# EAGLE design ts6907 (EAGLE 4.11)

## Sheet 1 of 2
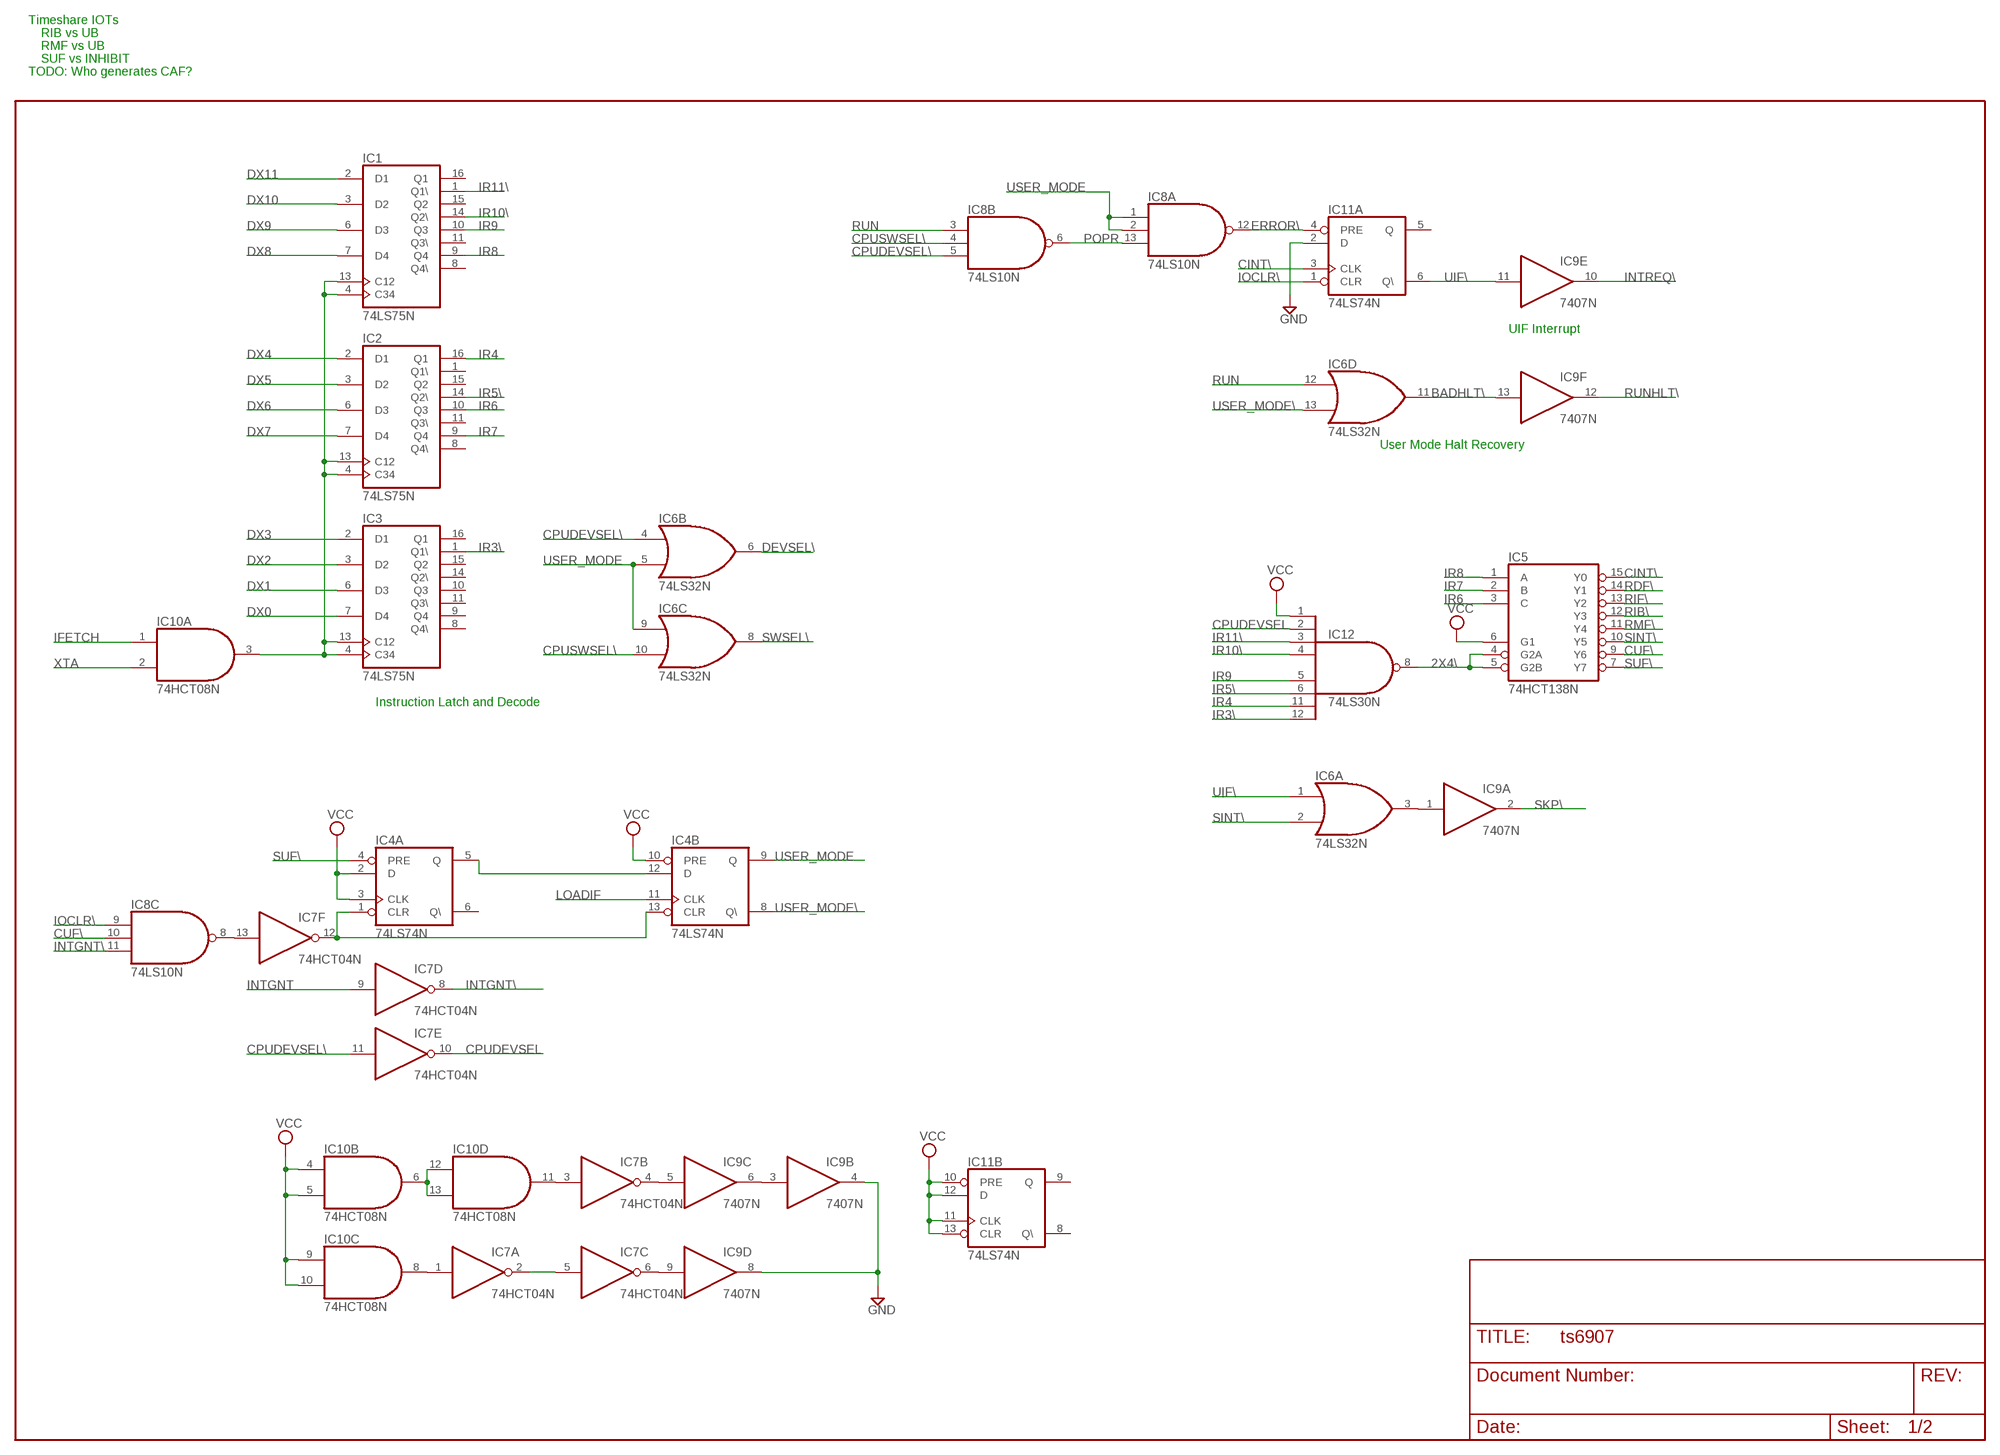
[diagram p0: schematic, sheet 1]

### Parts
IC1  74LS75N  [DIL16]
IC2  74LS75N  [DIL16]
IC3  74LS75N  [DIL16]
IC4  74LS74N  [DIL14]
IC5  74HCT138N  [DIL16]
IC6  74LS32N  [DIL14]
IC7  74HCT04N  [DIL14]
IC8  74LS10N  [DIL14]
IC9  7407N  [DIL14]
IC10  74HCT08N  [DIL14]
IC11  74LS74N  [DIL14]
IC12  74LS30N  [DIL14]

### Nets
2X4\: IC5.4(G2A) IC5.5(G2B) IC12.8(O)
BADHLT\: IC6.11(D:O) IC9.13(F:I)
CINT\: IC5.15(Y0) IC11.3(A:CLK)
CPUDEVSEL: IC7.10(E:O) IC12.2(I1)
CPUDEVSEL\: IC6.4(B:I0) IC7.11(E:I) IC8.5(B:I2) ; also sheet 2
CPUSWSEL\: IC6.10(C:I1) IC8.4(B:I1) ; also sheet 2
CUF\: IC5.9(Y6) IC8.10(C:I1)
DEVSEL\: IC6.6(B:O) ; also sheet 2
DX0: IC3.7(D4) ; also sheet 2
DX1: IC3.6(D3) ; also sheet 2
DX2: IC3.3(D2) ; also sheet 2
DX3: IC3.2(D1) ; also sheet 2
DX4: IC2.2(D1) ; also sheet 2
DX5: IC2.3(D2) ; also sheet 2
DX6: IC2.6(D3) ; also sheet 2
DX7: IC2.7(D4) ; also sheet 2
DX8: IC1.7(D4) ; also sheet 2
DX9: IC1.6(D3) ; also sheet 2
DX10: IC1.3(D2) ; also sheet 2
DX11: IC1.2(D1) ; also sheet 2
ERROR\: IC8.12(A:O) IC11.4(A:PRE)
GND: IC9.4(B:O) IC9.8(D:O) IC11.2(A:D) ; also sheet 2
IFETCH: IC10.1(A:I0) ; also sheet 2
INTGNT: IC7.9(D:I) ; also sheet 2
INTGNT\: IC7.8(D:O) IC8.11(C:I2)
INTREQ\: IC9.10(E:O) ; also sheet 2
IOCLR\: IC8.9(C:I0) IC11.1(A:CLR) ; also sheet 2
IR3\: IC3.1(Q1\) IC12.12(I7)
IR4: IC2.16(Q1) IC12.11(I6)
IR5\: IC2.14(Q2\) IC12.6(I5)
IR6: IC2.10(Q3) IC5.3(C)
IR7: IC2.9(Q4) IC5.2(B)
IR8: IC1.9(Q4) IC5.1(A)
IR9: IC1.10(Q3) IC12.5(I4)
IR10\: IC1.14(Q2\) IC12.4(I3)
IR11\: IC1.1(Q1\) IC12.3(I2)
LOADIF: IC4.11(B:CLK) ; also sheet 2
N$1: IC4.5(A:Q) IC4.12(B:D)
N$2: IC7.1(A:I) IC10.8(C:O)
N$3: IC1.4(C34) IC1.13(C12) IC2.4(C34) IC2.13(C12) IC3.4(C34) IC3.13(C12) IC10.3(A:O)
N$4: IC4.1(A:CLR) IC4.13(B:CLR) IC7.12(F:O)
N$5: IC7.3(B:I) IC10.11(D:O)
N$6: IC7.2(A:O) IC7.5(C:I)
N$7: IC10.6(B:O) IC10.12(D:I0) IC10.13(D:I1)
N$8: IC7.4(B:O) IC9.5(C:I)
N$9: IC7.6(C:O) IC9.9(D:I)
N$10: IC9.3(B:I) IC9.6(C:O)
N$11: IC6.3(A:O) IC9.1(A:I)
N$12: IC7.13(F:I) IC8.8(C:O)
POPR: IC8.6(B:O) IC8.13(A:I2)
RDF\: IC5.14(Y1)
RIB\: IC5.12(Y3)
RIF\: IC5.13(Y2)
RMF\: IC5.11(Y4)
RUN: IC6.12(D:I0) IC8.3(B:I0) ; also sheet 2
RUNHLT\: IC9.12(F:O) ; also sheet 2
SINT\: IC5.10(Y5) IC6.2(A:I1)
SKP\: IC9.2(A:O) ; also sheet 2
SUF\: IC4.4(A:PRE) IC5.7(Y7)
SWSEL\: IC6.8(C:O) ; also sheet 2
UIF\: IC6.1(A:I0) IC9.11(E:I) IC11.6(A:Q\)
USER_MODE: IC4.9(B:Q) IC6.5(B:I1) IC6.9(C:I0) IC8.1(A:I0) IC8.2(A:I1)
USER_MODE\: IC4.8(B:Q\) IC6.13(D:I1)
VCC: IC4.2(A:D) IC4.3(A:CLK) IC4.10(B:PRE) IC5.6(G1) IC10.4(B:I0) IC10.5(B:I1) IC10.9(C:I0) IC10.10(C:I1) IC11.10(B:PRE) IC11.11(B:CLK) IC11.12(B:D) IC11.13(B:CLR) IC12.1(I0) ; also sheet 2
XTA: IC10.2(A:I1) ; also sheet 2
Unconnected: IC1.8(Q4\) IC1.11(Q3\) IC1.15(Q2) IC1.16(Q1) IC2.1(Q1\) IC2.8(Q4\) IC2.11(Q3\) IC2.15(Q2) IC3.8(Q4\) IC3.9(Q4) IC3.10(Q3) IC3.11(Q3\) IC3.14(Q2\) IC3.15(Q2) IC3.16(Q1) IC4.6(A:Q\) IC11.5(A:Q) IC11.8(B:Q\) IC11.9(B:Q)

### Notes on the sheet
- Timeshare IOTs
- RIB vs UB
- RMF vs UB
- SUF vs INHIBIT
- TODO: Who generates CAF?
- UIF Interrupt
- User Mode Halt Recovery
- Instruction Latch and Decode

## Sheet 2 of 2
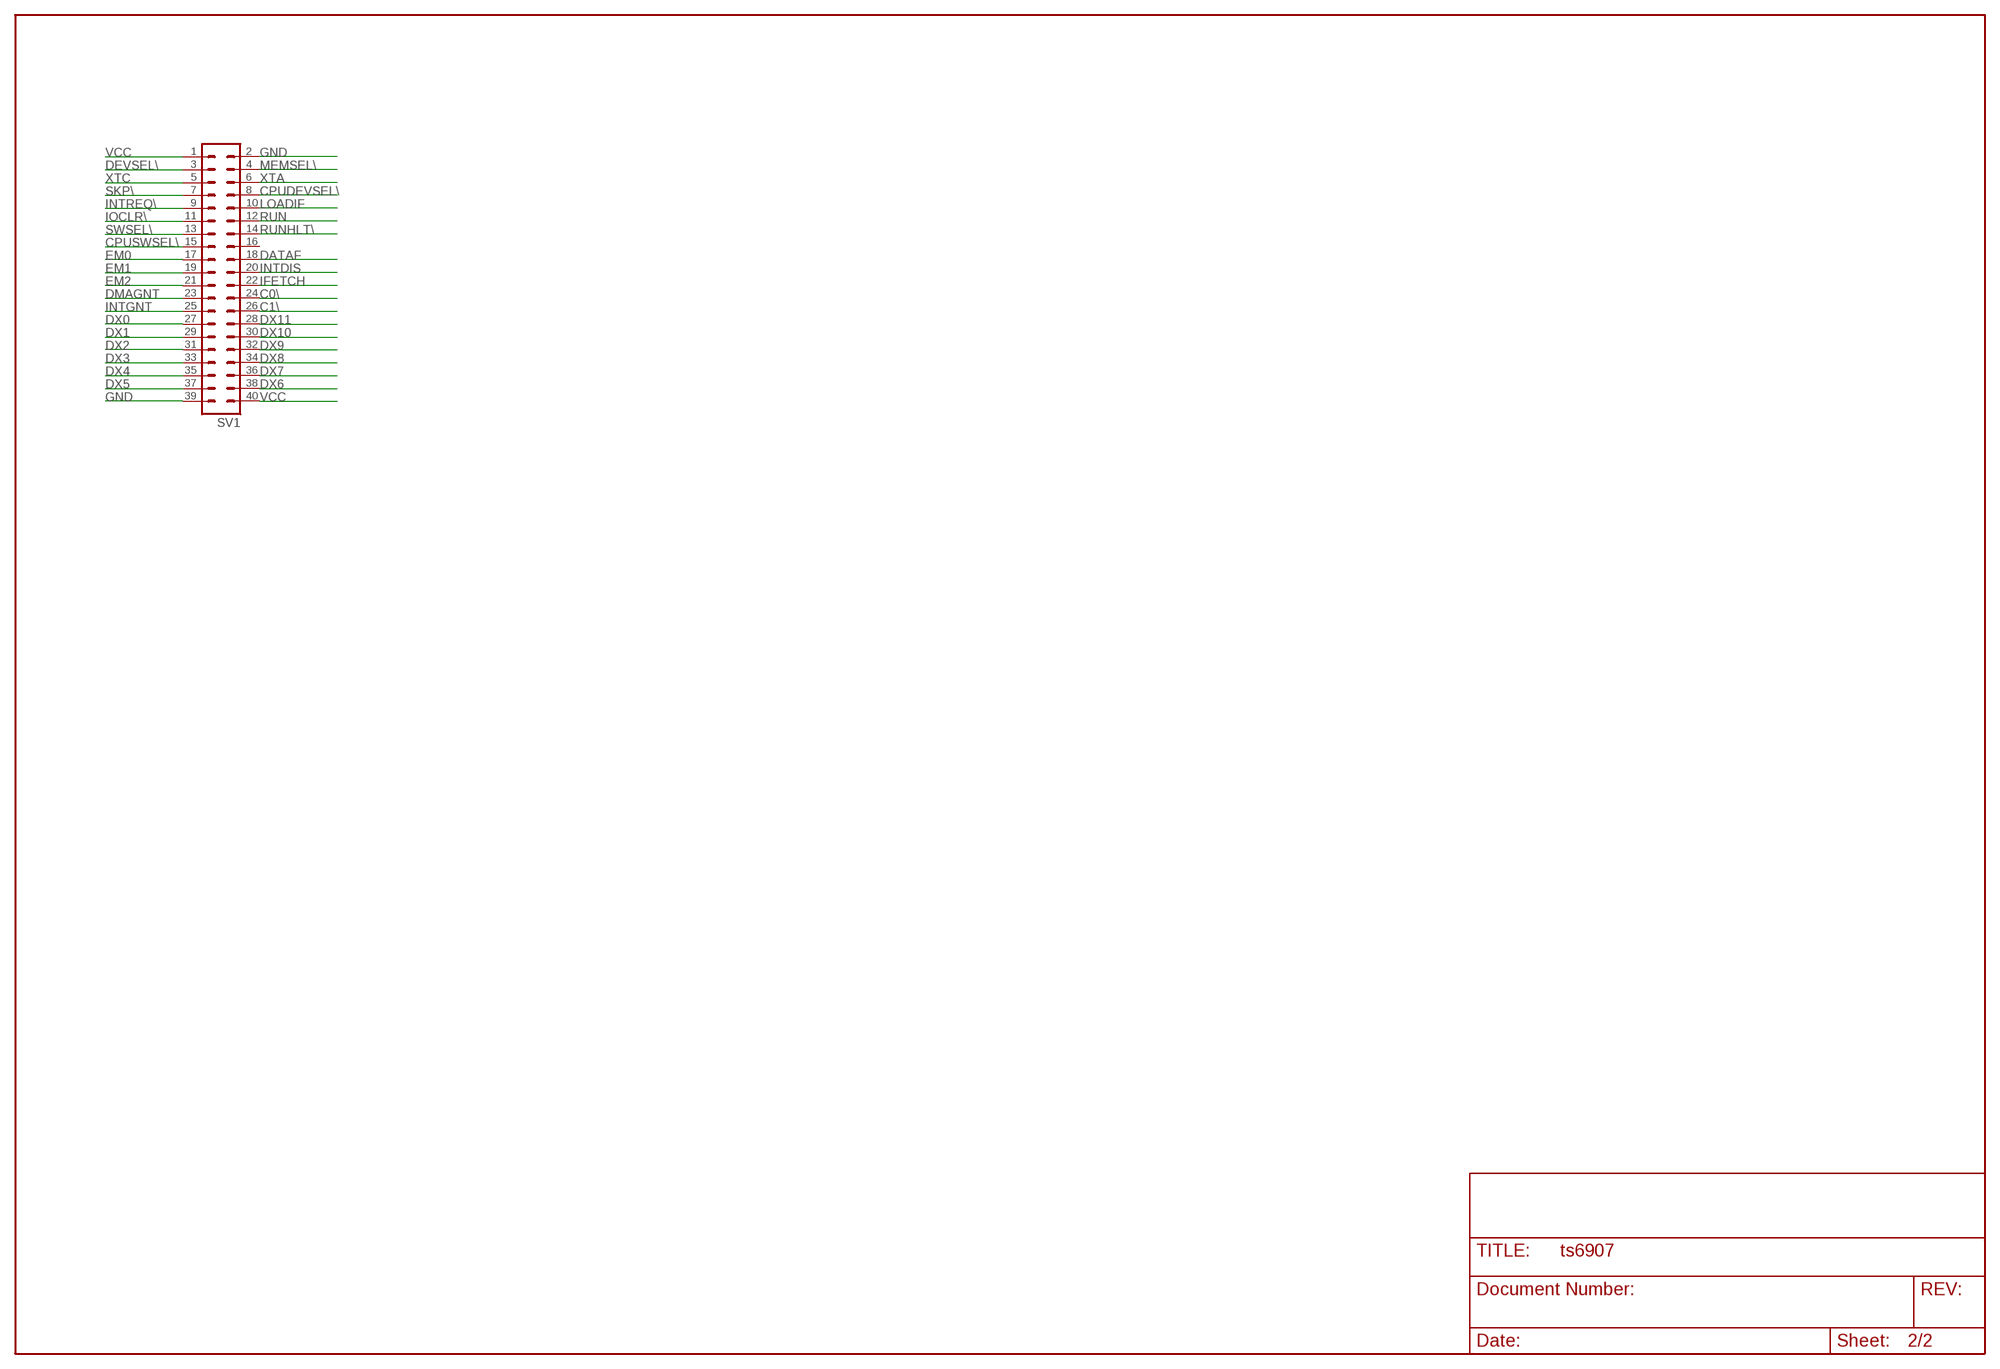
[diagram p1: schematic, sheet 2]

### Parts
SV1  MA20-2  [MA20-2]

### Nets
C0\: SV1.24
C1\: SV1.26
CPUDEVSEL\: SV1.8 ; also sheet 1
CPUSWSEL\: SV1.15 ; also sheet 1
DATAF: SV1.18
DEVSEL\: SV1.3 ; also sheet 1
DMAGNT: SV1.23
DX0: SV1.27 ; also sheet 1
DX1: SV1.29 ; also sheet 1
DX2: SV1.31 ; also sheet 1
DX3: SV1.33 ; also sheet 1
DX4: SV1.35 ; also sheet 1
DX5: SV1.37 ; also sheet 1
DX6: SV1.38 ; also sheet 1
DX7: SV1.36 ; also sheet 1
DX8: SV1.34 ; also sheet 1
DX9: SV1.32 ; also sheet 1
DX10: SV1.30 ; also sheet 1
DX11: SV1.28 ; also sheet 1
EM0: SV1.17
EM1: SV1.19
EM2: SV1.21
GND: SV1.2 SV1.39 ; also sheet 1
IFETCH: SV1.22 ; also sheet 1
INTDIS: SV1.20
INTGNT: SV1.25 ; also sheet 1
INTREQ\: SV1.9 ; also sheet 1
IOCLR\: SV1.11 ; also sheet 1
LOADIF: SV1.10 ; also sheet 1
MEMSEL\: SV1.4
RUN: SV1.12 ; also sheet 1
RUNHLT\: SV1.14 ; also sheet 1
SKP\: SV1.7 ; also sheet 1
SWSEL\: SV1.13 ; also sheet 1
VCC: SV1.1 SV1.40 ; also sheet 1
XTA: SV1.6 ; also sheet 1
XTC: SV1.5
Unconnected: SV1.16

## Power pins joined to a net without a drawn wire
GND: IC1.12(GND) IC2.12(GND) IC3.12(GND) IC4.7(P:GND) IC5.8(GND) IC6.7(P:GND) IC7.7(P:GND) IC8.7(P:GND) IC9.7(P:GND) IC10.7(P:GND) IC11.7(P:GND) IC12.7(GND)
VCC: IC1.5(VCC) IC2.5(VCC) IC3.5(VCC) IC4.14(P:VCC) IC5.16(VCC) IC6.14(P:VCC) IC7.14(P:VCC) IC8.14(P:VCC) IC9.14(P:VCC) IC10.14(P:VCC) IC11.14(P:VCC) IC12.14(VCC)

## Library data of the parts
IC1-IC3 = 74xx-jameco:74*75: 4-bit bistable LATCH
IC4 IC11 = 74xx-jameco:74*74: Dual D type positive edge triggered FLIP FLOP, preset and clear
IC5 = 74xx-jameco:74*138: 3-line to 8-line DECODER/DEMULTIPLEXER
IC6 = 74xx-jameco:74*32: Quad 2-input OR gate
IC7 = 74xx-jameco:74*04: Hex INVERTER
IC8 = 74xx-jameco:74*10: Triple 3-input NAND gate
IC9 = 74xx-jameco:74*07: Hex BUFFER, open collector high-voltage output
IC10 = 74xx-jameco:74*08: Quad 2-input AND gate
IC12 = 74xx-jameco:74*30: 8-input NAND gate
SV1 = con-lstb:MA20-2: PIN HEADER

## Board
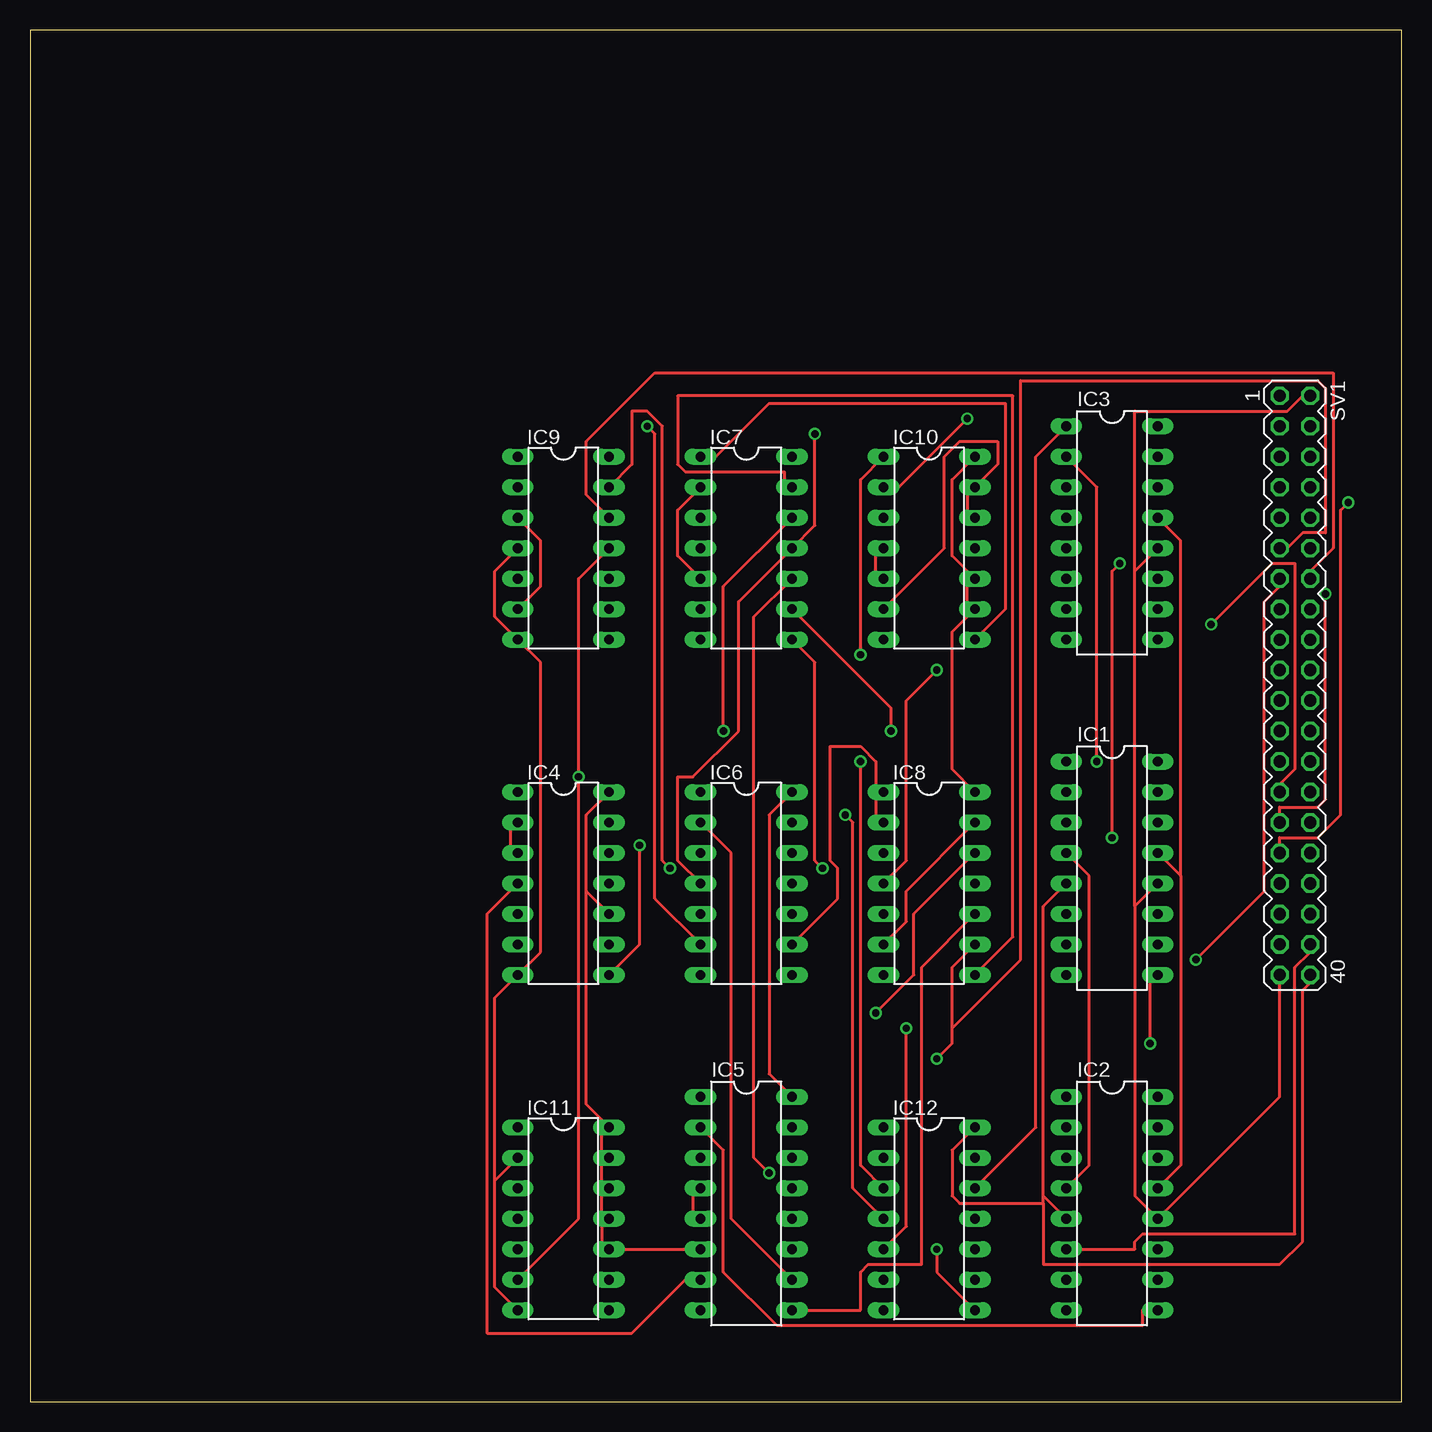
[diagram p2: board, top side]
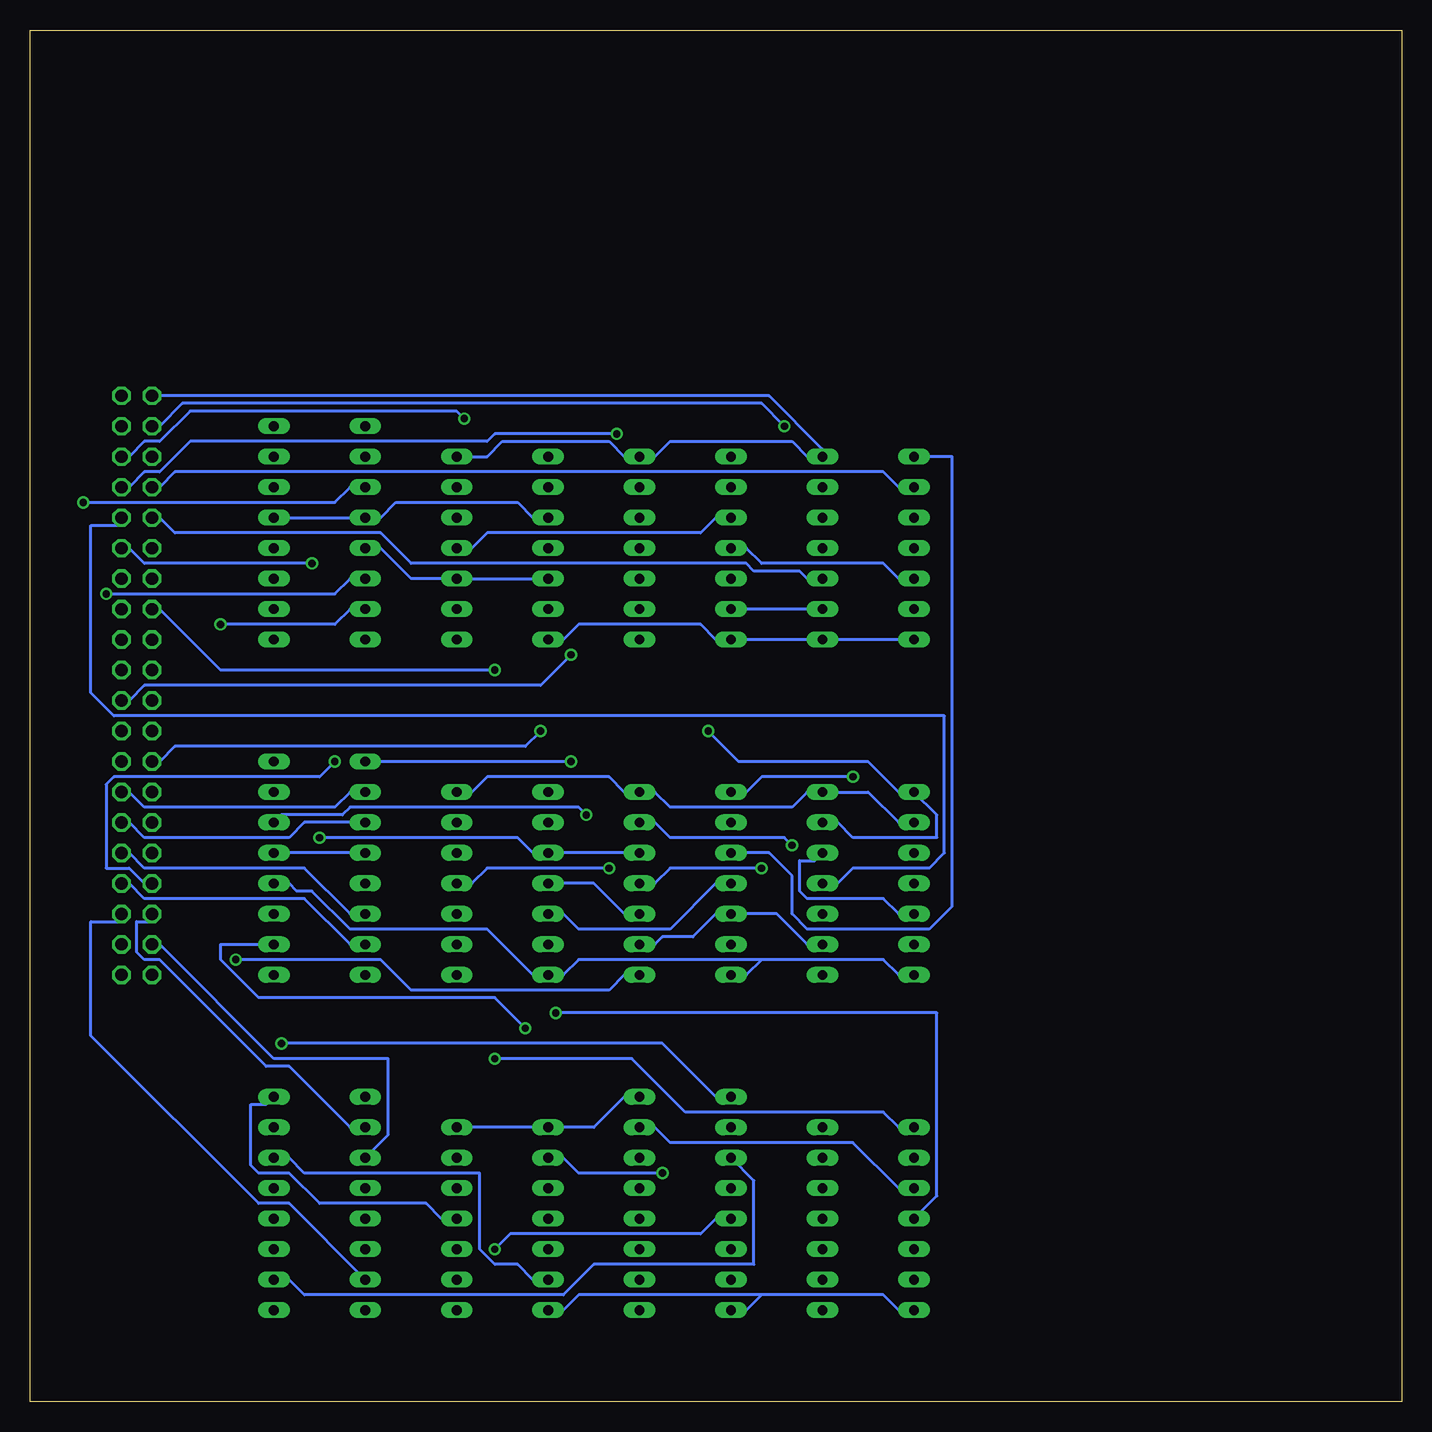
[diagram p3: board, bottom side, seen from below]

Size 114.3 x 114.3 mm. Coordinates in mm from the lower left corner, seen from the top.
Outline: 0,0 114.3,0 114.3,114.3 0,114.3 0,0
Copper layers (1*16): Top 0.035mm / dielectric 1.5mm / Bottom 0.035mm
Design rules "10mils": minimum track width 10mil, minimum drill 24mil, track to track 10mil, track to pad 10mil, pad to pad 10mil, via to via 10mil, smd to smd 10mil, copper to edge 40mil, drill to drill 10mil, minimum pad ring 10mil, minimum via ring 8mil, stop-mask expansion 0mil, vias tented up to drill 0mil, thermal gap 10mil

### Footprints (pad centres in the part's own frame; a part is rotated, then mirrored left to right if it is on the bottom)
DIL16 = drill 0.813 long: 1 -8.89,-3.81; 2 -6.35,-3.81; 3 -3.81,-3.81; 4 -1.27,-3.81; 5 1.27,-3.81; 6 3.81,-3.81; 7 6.35,-3.81; 8 8.89,-3.81; 9 8.89,3.81; 10 6.35,3.81; 11 3.81,3.81; 12 1.27,3.81; 13 -1.27,3.81; 14 -3.81,3.81; 15 -6.35,3.81; 16 -8.89,3.81
DIL14 = drill 0.813 long: 1 -7.62,-3.81; 2 -5.08,-3.81; 3 -2.54,-3.81; 4 0,-3.81; 5 2.54,-3.81; 6 5.08,-3.81; 7 7.62,-3.81; 8 7.62,3.81; 9 5.08,3.81; 10 2.54,3.81; 11 0,3.81; 12 -2.54,3.81; 13 -5.08,3.81; 14 -7.62,3.81
MA20-2 = drill 1.016 octagon: 1 -24.13,-1.27; 2 -24.13,1.27; 3 -21.59,-1.27; 4 -21.59,1.27; 5 -19.05,-1.27; 6 -19.05,1.27; 7 -16.51,-1.27; 8 -16.51,1.27; 9 -13.97,-1.27; 10 -13.97,1.27; 11 -11.43,-1.27; 12 -11.43,1.27; 13 -8.89,-1.27; 14 -8.89,1.27; 15 -6.35,-1.27; 16 -6.35,1.27; 17 -3.81,-1.27; 18 -3.81,1.27; 19 -1.27,-1.27; 20 -1.27,1.27; 21 1.27,-1.27; 22 1.27,1.27; 23 3.81,-1.27; 24 3.81,1.27; 25 6.35,-1.27; 26 6.35,1.27; 27 8.89,-1.27; 28 8.89,1.27; 29 11.43,-1.27; 30 11.43,1.27; 31 13.97,-1.27; 32 13.97,1.27; 33 16.51,-1.27; 34 16.51,1.27; 35 19.05,-1.27; 36 19.05,1.27; 37 21.59,-1.27; 38 21.59,1.27; 39 24.13,-1.27; 40 24.13,1.27

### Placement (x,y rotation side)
IC1  90.17,44.45 270 top
IC2  90.17,16.51 270 top
IC3  90.17,72.39 270 top
IC4  44.45,43.18 270 top
IC5  59.69,16.51 270 top
IC6  59.69,43.18 270 top
IC7  59.69,71.12 270 top
IC8  74.93,43.18 270 top
IC9  44.45,71.12 270 top
IC10  74.93,71.12 270 top
IC11  44.45,15.24 270 top
IC12  74.93,15.24 270 top
SV1  105.41,59.69 270 top

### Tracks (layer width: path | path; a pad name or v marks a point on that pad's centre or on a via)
2X4\  (via drill 0.61)
  Top 0.254: IC5.5 55.24,15.88 55.24,17.14 IC5.4 | v75.56,12.7 75.56,10.79 IC12.8
  Bottom 0.254: v75.56,12.7 74.3,13.97 58.42,13.97 57.15,15.24 IC5.5
BADHLT\  (via drill 0.61)
  Top 0.254: v53.34,44.45 52.7,45.09 52.7,81.28 51.44,82.55 50.16,82.55 50.16,78.11 IC9.13
  Bottom 0.254: v53.34,44.45 60.96,44.45 62.23,43.18 IC6.11
CINT\
  Bottom 0.254: IC11.3 41.91,17.78 45.72,21.59 60.96,21.59 62.23,22.86 IC5.15
CPUDEVSEL  (via drill 0.61)
  Top 0.254: v61.59,19.05 60.33,20.32 60.33,65.41 IC7.10
  Bottom 0.254: v61.59,19.05 68.58,19.05 69.85,20.32 IC12.2
CPUDEVSEL\  (via drill 0.61)
  Top 0.254: IC6.4 53.98,45.09 53.98,52.07 55.24,52.07 59.05,55.88 59.05,66.67 IC7.11 65.41,73.03 v65.41,80.64
  Bottom 0.254: IC6.4 57.15,43.18 60.96,39.37 68.58,39.37 69.85,40.64 IC8.5 | v65.41,80.64 75.56,80.64 76.2,80.01 100.97,80.01 103.5,77.47 104.78,77.47 106.05,76.2 SV1.8
CPUSWSEL\  (via drill 0.61)
  Top 0.254: v75.56,60.96 73.03,58.42 73.03,45.09 IC8.4
  Bottom 0.254: IC6.10 64.77,40.64 67.31,43.18 IC8.4 | v75.56,60.96 98.42,60.96 103.5,66.04 SV1.15
CUF\
  Top 0.254: IC5.9 69.22,7.62 69.22,10.79 69.85,11.43 74.3,11.43 74.3,36.2 IC8.10
DEVSEL\  (via drill 0.61)
  Top 0.254: v51.44,81.28 52.07,80.64 52.07,41.91 IC6.6
  Bottom 0.254: v51.44,81.28 53.34,83.19 101.6,83.19 103.5,81.28 SV1.3
DX0  (via drill 0.61)
  Top 0.254: v98.42,64.77 103.5,69.85 105.41,69.85 105.41,52.7 104.14,51.44 SV1.27
  Bottom 0.254: v98.42,64.77 88.9,64.77 87.63,66.04 IC3.7
DX1  (via drill 0.61)
  Top 0.254: v107.95,67.31 107.95,50.16 107.31,49.53 104.14,49.53 SV1.29
  Bottom 0.254: v107.95,67.31 88.9,67.31 87.63,68.58 IC3.6
DX2  (via drill 0.61)
  Top 0.254: v109.86,74.93 109.22,74.3 109.22,48.9 107.31,46.99 104.14,46.99 SV1.31
  Bottom 0.254: v109.86,74.93 88.9,74.93 87.63,76.2 IC3.3
DX3  (via drill 0.61)
  Top 0.254: v88.9,53.34 88.9,76.2 IC3.2
  Bottom 0.254: v88.9,53.34 90.17,52.07 107.31,52.07 107.95,51.44 107.95,44.45 106.05,44.45 104.78,43.18 SV1.33
DX4
  Bottom 0.254: IC2.2 87.63,22.86 92.71,27.94 94.61,27.94 103.5,36.83 104.78,36.83 105.41,37.47 105.41,40.01 104.14,40.01 SV1.35
DX5
  Bottom 0.254: IC2.3 84.45,22.23 84.45,28.57 93.98,28.57 103.5,38.1 SV1.37
DX6
  Top 0.254: IC2.6 92.08,12.7 92.08,13.34 92.71,13.97 105.41,13.97 105.41,36.2 106.68,37.47 SV1.38
DX7
  Bottom 0.254: IC2.7 92.71,16.51 95.25,16.51 109.22,30.48 109.22,40.01 106.68,40.01 SV1.36
DX8
  Bottom 0.254: IC1.7 87.63,38.1 91.44,41.91 104.78,41.91 106.05,43.18 SV1.34
DX9
  Bottom 0.254: IC1.6 87.63,40.64 91.44,44.45 104.78,44.45 106.05,45.72 SV1.32
DX10
  Bottom 0.254: IC1.3 91.44,48.26 92.71,46.99 104.78,46.99 106.05,48.26 SV1.30
DX11
  Bottom 0.254: IC1.2 87.63,50.8 88.9,49.53 104.78,49.53 106.05,50.8 SV1.28
ERROR\  (via drill 0.61)
  Top 0.254: v70.48,32.38 73.66,35.56 73.66,40.64 IC8.12
  Bottom 0.254: v70.48,32.38 38.73,32.38 38.73,17.14 IC11.4
GND
  Top 0.254: SV1.39 104.14,25.4 IC2.12 92.08,17.14 92.08,41.27 | IC1.12 92.08,41.27 | 92.08,41.27 92.08,69.22 | 92.08,69.22 IC3.12 | 92.08,69.22 92.08,82.55 104.78,82.55 106.05,83.82 SV1.2 | IC9.4 38.73,69.22 38.73,65.41 IC9.7 42.55,61.59 42.55,37.47 IC4.7 38.73,33.66 38.73,18.41 | 38.73,18.41 38.73,9.53 IC11.7 | 38.73,18.41 IC11.2
  Bottom 0.254: IC9.7 IC9.8 IC7.7 57.15,63.5 58.42,64.77 68.58,64.77 69.85,63.5 IC10.7 | 53.34,8.89 54.61,7.62 IC5.8 | 53.34,8.89 43.18,8.89 41.91,7.62 IC11.7 | 53.34,8.89 68.58,8.89 69.85,7.62 IC12.7 | 53.34,36.83 54.61,35.56 IC6.7 | 53.34,36.83 43.18,36.83 41.91,35.56 IC4.7 | 53.34,36.83 68.58,36.83 69.85,35.56 IC8.7 72.39,35.56 76.2,39.37 87.63,39.37 90.81,42.55 92.08,42.55 92.71,43.18 IC1.12
IFETCH  (via drill 0.61)
  Top 0.254: v69.22,62.23 69.22,76.83 IC10.1
  Bottom 0.254: v69.22,62.23 71.75,59.69 104.78,59.69 106.05,58.42 SV1.22
INTGNT  (via drill 0.61)
  Top 0.254: v71.75,55.88 71.75,57.78 IC7.9
  Bottom 0.254: v71.75,55.88 73.03,54.61 102.23,54.61 103.5,53.34 SV1.25
INTGNT\  (via drill 0.61)
  Top 0.254: v66.04,44.45 65.41,45.09 65.41,61.59 IC7.8
  Bottom 0.254: v66.04,44.45 76.2,44.45 77.47,43.18 IC8.11
INTREQ\
  Bottom 0.254: IC9.10 49.53,68.58 50.16,69.22 53.98,69.22 54.61,69.85 82.55,69.85 85.09,72.39 102.23,72.39 103.5,73.66 SV1.9
IOCLR\  (via drill 0.61)
  Top 0.254: v75.56,28.57 76.83,29.84 76.83,31.11 | 76.83,31.11 76.83,36.2 IC8.9 | 76.83,31.11 82.55,36.83 82.55,85.09 107.31,85.09 107.95,84.45 107.95,72.39 106.05,72.39 104.78,71.12 SV1.11
  Bottom 0.254: v75.56,28.57 64.14,28.57 59.69,24.13 43.18,24.13 41.91,22.86 IC11.1
IR3\
  Top 0.254: IC12.12 83.82,22.86 83.82,78.74 IC3.1
IR4
  Bottom 0.254: IC12.11 80.01,15.24 81.28,16.51 90.17,16.51 92.71,19.05 95.25,19.05 95.89,19.68 95.89,24.77 94.61,24.77 IC2.16
IR5\
  Bottom 0.254: IC12.6 72.39,10.16 73.66,11.43 75.56,11.43 76.83,12.7 76.83,19.05 91.44,19.05 92.71,20.32 IC2.14
IR6
  Bottom 0.254: IC5.3 53.98,18.41 53.98,11.43 67.31,11.43 69.85,8.89 91.44,8.89 92.71,10.16 IC2.10
IR7
  Top 0.254: IC5.2 57.78,20.95 57.78,10.79 62.23,6.35 92.71,6.35 92.71,7.62 IC2.9
IR8  (via drill 0.61)
  Top 0.254: v93.34,29.84 93.34,34.92 IC1.9
  Bottom 0.254: v93.34,29.84 61.59,29.84 57.15,25.4 IC5.1
IR9  (via drill 0.61)
  Top 0.254: v73.03,31.11 73.03,14.61 IC12.5
  Bottom 0.254: v73.03,31.11 75.56,33.66 95.25,33.66 98.42,36.83 98.42,38.1 IC1.10
IR10\  (via drill 0.61)
  Top 0.254: v67.94,48.9 68.58,48.26 68.58,17.78 IC12.4
  Bottom 0.254: v67.94,48.9 68.58,49.53 87.63,49.53 88.27,48.9 93.34,48.9 IC1.14
IR11\  (via drill 0.61)
  Top 0.254: v69.22,53.34 69.22,19.68 IC12.3
  Bottom 0.254: v69.22,53.34 IC1.1
LOADIF
  Bottom 0.254: IC4.11 46.99,43.18 45.72,44.45 39.37,44.45 38.1,45.72 38.1,57.15 107.31,57.15 109.22,59.05 109.22,73.03 106.68,73.03 SV1.10
N$1
  Bottom 0.254: IC4.5 41.91,40.64 43.18,41.91 49.53,41.91 50.16,42.55 50.16,45.09 48.9,45.09 IC4.12
N$2
  Top 0.254: IC7.1 57.15,78.74 61.59,83.19 81.28,83.19 81.28,66.04 IC10.8
N$3
  Top 0.254: IC2.4 88.27,19.68 88.27,43.81 IC1.4 | 95.89,43.81 95.89,19.68 IC2.13 | IC1.13 95.89,43.81 | 95.89,43.81 95.89,71.75 IC3.13
  Bottom 0.254: IC10.3 72.39,73.66 73.66,74.93 83.82,74.93 85.09,73.66 IC3.4 IC3.13 | IC1.4 IC1.13
N$4  (via drill 0.61)
  Top 0.254: v57.78,55.88 57.78,67.94 IC7.12
  Bottom 0.254: IC4.13 46.99,48.26 45.72,46.99 38.73,46.99 38.73,48.9 IC4.1 41.91,50.8 44.45,53.34 55.24,53.34 v57.78,55.88
N$5
  Bottom 0.254: IC7.3 57.15,73.66 58.42,72.39 76.2,72.39 77.47,71.12 IC10.11
N$6
  Top 0.254: IC7.5 53.98,70.48 53.98,74.3 IC7.2
N$7
  Top 0.254: IC10.6 76.2,71.12 76.2,78.74 77.47,80.01 80.64,80.01 80.64,78.11 IC10.13 78.11,75.56 78.11,74.3 IC10.12
N$8
  Bottom 0.254: IC9.5 41.91,68.58 43.18,69.85 53.34,69.85 54.61,71.12 IC7.4
N$9
  Bottom 0.254: IC9.9 IC7.6
N$10
  Top 0.254: IC9.6 42.55,67.94 42.55,71.75 IC9.3
N$11
  Bottom 0.254: IC6.3 52.7,45.72 50.8,43.81 50.8,40.64 49.53,39.37 39.37,39.37 37.47,41.27 37.47,78.74 IC9.1
N$12
  Top 0.254: IC8.8 81.92,38.73 81.92,83.82 53.98,83.82 53.98,78.11 54.61,77.47 62.87,77.47 62.87,76.83 IC7.13
POPR
  Top 0.254: IC8.6 73.03,40.01 73.03,42.55 IC8.13
RUN  (via drill 0.61)
  Top 0.254: v90.81,69.85 90.17,69.22 v90.17,46.99
  Bottom 0.254: IC6.12 IC8.3 72.39,45.72 73.66,46.99 v90.17,46.99 | v90.81,69.85 104.78,69.85 106.05,71.12 SV1.12
RUNHLT\
  Top 0.254: IC9.12 46.35,75.56 46.35,80.01 52.07,85.72 108.58,85.72 108.58,71.12 106.68,69.22 SV1.14
SINT\
  Top 0.254: IC5.10 58.42,15.24 58.42,45.72 IC6.2
SKP\
  Bottom 0.254: IC9.2 41.91,76.2 43.18,77.47 102.23,77.47 103.5,76.2 SV1.7
SUF\
  Top 0.254: IC5.7 54.61,10.16 50.16,5.71 38.1,5.71 38.1,40.64 IC4.4
SWSEL\  (via drill 0.61)
  Top 0.254: v97.16,36.83 102.87,42.55 102.87,66.67 104.14,67.94 SV1.13
  Bottom 0.254: v97.16,36.83 85.09,36.83 82.55,34.29 66.04,34.29 64.77,35.56 IC6.8
UIF\  (via drill 0.61)
  Top 0.254: IC11.6 45.72,15.24 v45.72,52.07 45.72,68.58 IC9.11
  Bottom 0.254: v45.72,52.07 53.34,52.07 54.61,50.8 IC6.1
USER_MODE
  Top 0.254: IC8.2 70.48,48.9 70.48,50.16 IC8.1 70.48,51.44 70.48,53.34 69.22,54.61 66.67,54.61 66.67,45.09 67.31,44.45 67.31,41.91 IC6.9
  Bottom 0.254: IC4.9 49.53,38.1 52.07,40.64 IC6.5 57.15,40.64 59.05,38.73 61.59,38.73 62.23,38.1 IC6.9
USER_MODE\  (via drill 0.61)
  Top 0.254: v50.8,46.35 50.8,38.1 IC4.8
  Bottom 0.254: v50.8,46.35 51.44,46.99 60.96,46.99 62.23,48.26 IC6.13
VCC
  Top 0.254: 84.45,17.14 84.45,41.27 IC1.5 | 84.45,17.14 IC2.5 | 84.45,16.51 84.45,17.14 | 84.45,16.51 84.45,11.43 104.14,11.43 106.05,13.34 106.05,34.29 106.68,34.92 SV1.40 | 84.45,16.51 77.47,16.51 76.83,17.14 76.83,20.95 IC12.14 | IC10.5 70.48,69.22 70.48,70.48 IC10.4 | IC10.14 76.83,76.83 76.83,70.48 IC10.10 78.11,67.94 78.11,66.67 IC10.9 76.83,64.14 76.83,52.7 IC8.14 | IC5.6 IC11.10 47.62,13.34 47.62,14.61 IC11.11 47.62,15.88 47.62,17.14 IC11.12 47.62,18.41 47.62,19.68 IC11.13 47.62,20.95 47.62,22.23 IC11.14 46.35,24.77 46.35,42.55 | IC4.3 40.01,46.35 40.01,47.62 IC4.2 | 46.35,42.55 46.35,48.9 IC4.14 | 46.35,42.55 IC4.10 | IC5.16 61.59,27.3 61.59,48.9 IC6.14
  Bottom 0.254: IC5.16 64.77,25.4 67.31,22.86 IC12.1 IC12.14 | SV1.1 52.7,83.82 48.26,79.38 IC9.14 49.53,78.74 50.8,80.01 60.96,80.01 62.23,78.74 IC7.14 64.77,78.74 66.04,80.01 74.93,80.01 76.2,78.74 IC10.14 | IC3.5 85.09,71.12 82.55,68.58 IC10.10 IC10.5 | IC8.14 77.47,50.8 76.2,52.07 66.04,52.07 64.77,50.8 IC6.14 62.23,50.8 60.96,49.53 50.8,49.53 49.53,50.8 IC4.14 44.45,50.8 41.91,48.26 IC4.2
XTA  (via drill 0.61)
  Top 0.254: v78.11,81.92 72.39,76.2 IC10.2
  Bottom 0.254: v78.11,81.92 78.74,82.55 100.97,82.55 103.5,80.01 104.78,80.01 106.05,78.74 SV1.6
